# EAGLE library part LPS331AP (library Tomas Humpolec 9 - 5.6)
LPS331AP MEMS pressure sensor: 260-1260 mbar absolute digital output barometer Features ? 260 to 1260 mbar absolute pressure range ? High-resolution mode: 0.020 mbar RMS ? Low power consumption: ? Low resolution mode: 5.5 ?A ? High resolution mode: 30 ?A ? High overpressure capability: 20x full scale ? Embedded temperature compensation ? Embedded 24-bit ADC ? Selectable ODR from 1 Hz to 25 Hz ? SPI and I2C interfaces ? Supply voltage: 1.71 to 3.6 V ? High shock survivability: 10,000g ? Small and thin package ? ECOPACK® lead-free compliant Applications ? Altimeter and barometer for portable devices ? GPS applications ? Weather station equipment ? Sport watches Description The LPS331AP is an ultra compact absolute piezoresistive pressure sensor. It includes a monolithic sensing element and an IC interface able to take the information from the sensing element and to provide a digital signal to the external world. The sensing element consists of a suspended membrane realized inside a single mono-silicon substrate. It is capable to detecting pressure and is manufactured using a dedicated process developed by ST, called VENSENS. The VENSENS process allows to build a monosilicon membrane above an air cavity with controlled gap and defined pressure. The membrane is very small compared to the traditionally built silicon micromachined membranes. Membrane breakage is prevented by an intrinsic mechanical stopper. The IC interface is manufactured using a standard CMOS process that allows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
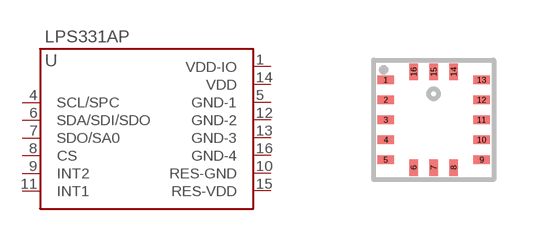
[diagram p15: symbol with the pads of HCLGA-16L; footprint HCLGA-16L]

Designator prefix -

## LPS331AP  [HCLGA-16L]
1  VDD-IO  pwr
4  SCL/SPC
5  GND-1  pwr
6  SDA/SDI/SDO
7  SDO/SA0
8  CS
9  INT2
10  RES-GND  in
11  INT1
12  GND-2  pwr
13  GND-3  pwr
14  VDD  pwr
15  RES-VDD  in
16  GND-4  pwr

## Footprint HCLGA-16L (pad centres in mm)
Package outline for HCLGA-16L (3x3x1mm)
smd 0.406 x 0.203: 1 0.3,2.5; 2 0.3,2; 3 0.3,1.5; 4 0.3,1; 5 0.3,0.5; 9 2.7,0.5; 10 2.7,1; 11 2.7,1.5; 12 2.7,2; 13 2.7,2.5
smd 0.203 x 0.406: 6 1,0.3; 7 1.5,0.3; 8 2,0.3; 14 2,2.7; 15 1.5,2.7; 16 1,2.7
